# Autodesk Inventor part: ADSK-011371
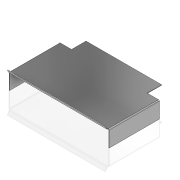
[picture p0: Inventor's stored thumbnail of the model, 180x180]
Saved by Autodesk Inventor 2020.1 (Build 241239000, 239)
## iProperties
Created: 1999-12
Part Number: ADSK-011371
Material: 1.0312 DC05
Document SubType Name: Tôlerie
Designer: glanglot
Density: 1 g/cm^3
Sheet Metal Rule: Stahlblech 1.0312 - DC05 -   1.5mm
Appearance: Chrom - poliert
Mass: 117.903 g
Surface Area: 1590.74 cm^2
Volume: 117.903 cm^3
Flat Pattern Width: 21.5298 cm
Flat Pattern Length: 40.7786 cm
Flat Pattern Area: 877.954 cm^2
Sheet Metal Width: 215,29785 mm
Sheet Metal Length: 407,78584 mm
Sheet Metal Area: 87795,41264 mm^2
Control State: 0
Checked Out: False
Master: False
Shininess: 60.0
Length Units: 11269
Angle Units: 11279
Time Units: 11290
Mass Units: 11283
Length Display Precision: 5
Angle Display Precision: 5
Compacted: True
G_L: 407,8x215,3 mm
Thickness: 1,50000 mm
Dimensions: 311x61,1x210,3 mm
Mass: 0,118 kg
Semi finished: Stahlblech 1.0312 - DC05 -   1.5mm
Density: 0.0
Volumn: 0.0
Area: 0.0
PropertySet Name: Model Information
Author: glanglot
Revision Number: -
Title: ADSK-011371
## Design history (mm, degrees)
sketch "Sketch1"
  geometry: L1 (-155.5, 0)-(155.5, 0); 2 further points
  constraints: 2 end point, 1 coincident, 1 horizontal, 1 midpoint
  dimensions: "d95" = 311 distance of L1.start L1.end
sketch "Skizze6"
  geometry: L1 through (0, 100.5) direction (0, -1); L2 through (25.5, 0) direction (1, -1.55e-49); L3 (51, 0)-(51, 201); L4 (51, 201)-(0, 201)
  constraints: 6 end point, 1 horizontal, 1 perpendicular, 1 vertical
feature "Grobblech3" dims "d47" = 1.5 (= Thickness), "d70" = 1.5 (= BendReliefWidth), "d71" = 0.75 (= BendReliefDepth), "d72" = 3 (= MinimumRemnant), "d73" = 1.5 (= TransitionRadius), "d74" = 3, "d75" = 0, "d76" = 51, "d77" = 90 deg, "d78" = 1.5 (= BendRadius), "d79" = 6 (= CornerReliefSize), "d80" = 1.5 (= TailleJeu), "d81" = 1.5 (= TailleRayonJacobi), "SeamGap" = 0.00508
feature "Biegung3" dims "d47" = 1.5 (= Thickness), "d70" = 1.5 (= BendReliefWidth), "d71" = 0.75 (= BendReliefDepth), "d72" = 3 (= MinimumRemnant), "d73" = 1.5 (= TransitionRadius), "d76" = 51, "d77" = 90 deg, "d78" = 1.5 (= BendRadius), "SeamGap" = 0.00508
node "Lasche2"
feature "Ecke3" dims "d76" = 51, "d77" = 90 deg, "d79" = 6 (= CornerReliefSize), "d80" = 1.5 (= TailleJeu), "d81" = 1.5 (= TailleRayonJacobi)
sketch "Skizze7"
  geometry: L1 through (-151.75, 0) direction (1, 3.03e-20); L2 through (0, 6.25) direction (1.5e-16, 1); L3 (0, 12.5)-(-303.5, 12.5); L4 (-303.5, 12.5)-(-303.5, 0)
  constraints: 6 end point, 1 horizontal, 1 perpendicular, 1 vertical
feature "Grobblech4" dims "d47" = 1.5 (= Thickness), "d82" = 1.5 (= BendReliefWidth), "d83" = 0.75 (= BendReliefDepth), "d84" = 3 (= MinimumRemnant), "d85" = 1.5 (= TransitionRadius), "d86" = 12.5, "d87" = 60 deg, "d88" = 1.5 (= BendRadius), "d89" = 6 (= CornerReliefSize), "d90" = 1.5 (= TailleJeu), "d91" = 1.5 (= TailleRayonJacobi), "SeamGap" = 0.00508
feature "Biegung4" dims "d47" = 1.5 (= Thickness), "d82" = 1.5 (= BendReliefWidth), "d83" = 0.75 (= BendReliefDepth), "d84" = 3 (= MinimumRemnant), "d85" = 1.5 (= TransitionRadius), "d86" = 12.5, "d87" = 60 deg, "d88" = 1.5 (= BendRadius), "SeamGap" = 0.00508
node "Lasche3"
feature "Ecke4" dims "d86" = 12.5, "d87" = 60 deg, "d89" = 6 (= CornerReliefSize), "d90" = 1.5 (= TailleJeu), "d91" = 1.5 (= TailleRayonJacobi)
feature "Grobblech1" dims "d47" = 1.5 (= Thickness), "d48" = 1.5 (= BendReliefWidth), "d49" = 0.75 (= BendReliefDepth), "d50" = 3 (= MinimumRemnant), "d51" = 1.5 (= TransitionRadius), "d52" = 204, "d53" = 1.5 (= BendRadius), "d54" = 1.5, "d55" = 6 (= CornerReliefSize), "d56" = 1.5 (= TailleJeu), "d57" = 1.5 (= TailleRayonJacobi), "SeamGap" = 0.00508
node "Volumenkörper2"
  node "Konturlasche1"
  node "Lasche1"
  node "Extrusion4" dims "d45" = 25.4, "d46" = 0
feature "Biegung1" dims "d47" = 1.5 (= Thickness), "d48" = 1.5 (= BendReliefWidth), "d49" = 0.75 (= BendReliefDepth), "d50" = 3 (= MinimumRemnant), "d51" = 1.5 (= TransitionRadius), "d53" = 1.5 (= BendRadius), "d54" = 1.5, "SeamGap" = 0.00508
feature "Ecke1" dims "d54" = 1.5, "d55" = 6 (= CornerReliefSize), "d56" = 1.5 (= TailleJeu), "d57" = 1.5 (= TailleRayonJacobi)
sketch "Skizze5"
  geometry: L1 (0, -204)-(0, -3); L2 (0, -3)-(-51, -3); L3 (-51, -3)-(-51, -204); L4 (-51, -204)-(0, -204)
  constraints: 8 end point
feature "Grobblech2" dims "d47" = 1.5 (= Thickness), "d58" = 1.5 (= BendReliefWidth), "d59" = 0.75 (= BendReliefDepth), "d60" = 3 (= MinimumRemnant), "d61" = 1.5 (= TransitionRadius), "d62" = 3, "d63" = 0, "d64" = 51, "d65" = 90 deg, "d66" = 1.5 (= BendRadius), "d67" = 6 (= CornerReliefSize), "d68" = 1.5 (= TailleJeu), "d69" = 1.5 (= TailleRayonJacobi), "SeamGap" = 0.00508
feature "Biegung2" dims "d47" = 1.5 (= Thickness), "d58" = 1.5 (= BendReliefWidth), "d59" = 0.75 (= BendReliefDepth), "d60" = 3 (= MinimumRemnant), "d61" = 1.5 (= TransitionRadius), "d64" = 51, "d65" = 90 deg, "d66" = 1.5 (= BendRadius), "SeamGap" = 0.00508
feature "Ecke2" dims "d64" = 51, "d65" = 90 deg, "d67" = 6 (= CornerReliefSize), "d68" = 1.5 (= TailleJeu), "d69" = 1.5 (= TailleRayonJacobi)
sketch "Sketch4"
  geometry: L1 (0, 102)-(305, 102) reference; L2 (308, 102)-(308, -99) reference; L3 (308, 102)-(270, 102); L4 (270, 102)-(270, 57); L5 (270, 57)-(308, 57); L6 (308, 57)-(308, 102); L7 (-3, 102)-(35, 102); L8 (35, 102)-(35, 57); L9 (35, 57)-(-3, 57); L10 (-3, 57)-(-3, 102); 3 further points; 1 other entity
  constraints: 16 end point, 4 parallel, 2 horizontal, 2 perpendicular, 1 point on line, 1 other
  dimensions: "d92" = 38 distance between parallel lines of L6 L4; "d93" = 38 dimension on L8 (= d92); "d94" = 45 distance of L7.end L8.end
node "Solide1"
node "Corps solides"
node "Corps surfaciques"
feature "Definition1"
other parameters: "WIDTH" = 304.8 [user parameter], "Thickness" = 1.5 (derived), "BendRadius" = 1.5 (= Thickness), "BendReliefWidth" = 1.5 (= Thickness), "BendReliefDepth" = 0.75 (= 0.5 x Thickness), "CornerReliefSize" = 6 (= 4 x Thickness), "MinimumRemnant" = 3 (= 2 x Thickness), "TransitionRadius" = 1.5 (= BendRadius), "TailleRayonJacobi" = 1.5 (= BendRadius), "TailleJeu" = 1.5 (= Thickness), "WIDTH" = 304.8, "BendRadius" = 1.5, "BendReliefDepth" = 0.75, "BendReliefWidth" = 1.5, "CornerReliefSize" = 6, "MinimumRemnant" = 3, "TailleJeu" = 1.5, "TailleRayonJacobi" = 1.5, "Thickness" = 1.5, "TransitionRadius" = 1.5
